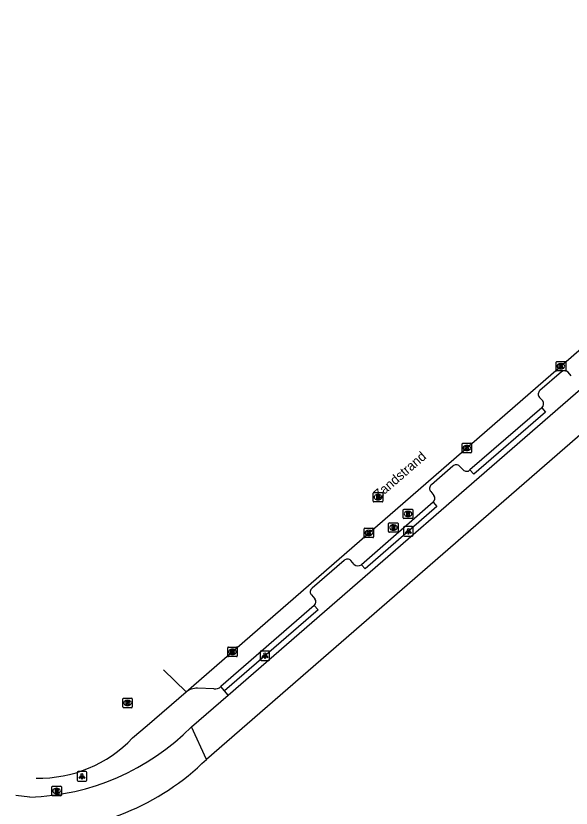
# Model space of a CAD drawing. Extents: x 155640 to 156810, y 382822 to 384046.
# Drawn here: x 156392.5 to 156451, y 383942 to 384025.5 of the extents above; entities that cross this region are included whole.
import ezdxf

# ---------------------------------------------------------------- set-up
doc = ezdxf.new("R2010")
doc.units = 0
for name, color, linetype in [('IMGEO_Berm_groen', 7, 'Continuous'), ('IMGEO_Berm_open', 7, 'Continuous'), ('IMGEO_Fietspad_gesloten', 7, 'Continuous'), ('IMGEO_Kolk', 7, 'Continuous'), ('IMGEO_Lichtpunt', 7, 'Continuous'), ('IMGEO_Openbare_ruimte_label', 7, 'Continuous'), ('IMGEO_Parkeervlak_open', 7, 'Continuous'), ('IMGEO_Rijbaan_lokaal_gesloten', 7, 'Continuous'), ('IMGEO_Rioolput', 7, 'Continuous'), ('IMGEO_Verkeerseiland_open', 7, 'Continuous')]:
    doc.layers.add(name, color=color, linetype=linetype)

msp = doc.modelspace()

# ---------------------------------------------------------------- linework, layer by layer
at = {"layer": 'IMGEO_Berm_groen'}
msp.add_lwpolyline([(156414.861, 383953.961), (156414.47, 383954.414)], dxfattribs=at)
at = {"layer": 'IMGEO_Berm_open'}
for points in [[(156447.898, 383984.213), (156448.29, 383983.759), (156440.715, 383977.209), (156440.323, 383977.663)], [(156423.925, 383963.387), (156424.318, 383962.933), (156414.47, 383954.414)], [(156414.47, 383954.414), (156414.077, 383954.868)]]:
    msp.add_lwpolyline(points, dxfattribs=at)
at = {"layer": 'IMGEO_Fietspad_gesloten'}
for points in [[(156493.456, 384017.313), (156481.006, 384006.405), (156479.158, 384005), (156473.402, 384000), (156464.513, 383992.278), (156412.558, 383947.186)], [(156414.861, 383953.961), (156456.26, 383989.906)], [(156410.985, 383950.596), (156414.861, 383953.961)], [(156412.558, 383947.186), (156410.985, 383950.596)], [(156393.957, 383943.215), (156392.486, 383943.386)]]:
    msp.add_lwpolyline(points, dxfattribs=at)
for centre, radius, start, end in [((156393.202, 383968.289), 25.085, 271.72451, 315.14534), ((156394.176, 383965.799), 26.16, 269.75761, 314.64317)]:
    msp.add_arc(centre, radius, start, end, dxfattribs=at)
at = {"layer": 'IMGEO_Kolk'}
for p, q in [((156449.405, 383988.162), (156449.405, 383989.014)), ((156449.48, 383989.088), (156450.332, 383989.088)), ((156449.893, 383988.868), (156449.918, 383988.868)), ((156450.406, 383989.014), (156450.406, 383988.162)), ((156450.332, 383988.088), (156449.48, 383988.088)), ((156449.916, 383988.308), (156449.891, 383988.308)), ((156439.498, 383979.551), (156439.498, 383980.403)), ((156439.573, 383980.477), (156440.425, 383980.477)), ((156439.986, 383980.257), (156440.011, 383980.257)), ((156440.499, 383980.403), (156440.499, 383979.551)), ((156440.425, 383979.477), (156439.573, 383979.477)), ((156440.009, 383979.697), (156439.984, 383979.697)), ((156429.17, 383970.608), (156429.17, 383971.46)), ((156429.245, 383971.534), (156430.097, 383971.534)), ((156429.658, 383971.314), (156429.683, 383971.314)), ((156430.171, 383971.46), (156430.171, 383970.608)), ((156430.097, 383970.534), (156429.245, 383970.534)), ((156429.681, 383970.754), (156429.656, 383970.754)), ((156414.804, 383958.086), (156414.804, 383958.938)), ((156414.879, 383959.012), (156415.731, 383959.012)), ((156415.292, 383958.792), (156415.317, 383958.792)), ((156415.805, 383958.938), (156415.805, 383958.086)), ((156415.731, 383958.012), (156414.879, 383958.012)), ((156415.315, 383958.232), (156415.29, 383958.232))]:
    msp.add_line(p, q, dxfattribs=at)
for points in [[(156449.405, 383988.162), (156449.405, 383989.014)], [(156449.48, 383989.088), (156450.332, 383989.088)], [(156449.726, 383988.788), (156449.849, 383988.788), (156449.849, 383988.637), (156449.979, 383988.788), (156450.143, 383988.788), (156449.997, 383988.637), (156450.15, 383988.388), (156449.998, 383988.388), (156449.913, 383988.552), (156449.849, 383988.485), (156449.849, 383988.388), (156449.726, 383988.388), (156449.726, 383988.788)], [(156450.406, 383989.014), (156450.406, 383988.162)], [(156450.332, 383988.088), (156449.48, 383988.088)], [(156439.498, 383979.551), (156439.498, 383980.403)], [(156439.573, 383980.477), (156440.425, 383980.477)], [(156439.819, 383980.177), (156439.942, 383980.177), (156439.942, 383980.026), (156440.072, 383980.177), (156440.236, 383980.177), (156440.09, 383980.026), (156440.243, 383979.777), (156440.091, 383979.777), (156440.006, 383979.941), (156439.942, 383979.874), (156439.942, 383979.777), (156439.819, 383979.777), (156439.819, 383980.177)], [(156440.499, 383980.403), (156440.499, 383979.551)], [(156440.425, 383979.477), (156439.573, 383979.477)], [(156429.17, 383970.608), (156429.17, 383971.46)], [(156429.245, 383971.534), (156430.097, 383971.534)], [(156429.491, 383971.234), (156429.614, 383971.234), (156429.614, 383971.083), (156429.744, 383971.234), (156429.908, 383971.234), (156429.762, 383971.083), (156429.915, 383970.834), (156429.763, 383970.834), (156429.678, 383970.998), (156429.614, 383970.931), (156429.614, 383970.834), (156429.491, 383970.834), (156429.491, 383971.234)], [(156430.171, 383971.46), (156430.171, 383970.608)], [(156430.097, 383970.534), (156429.245, 383970.534)], [(156414.804, 383958.086), (156414.804, 383958.938)], [(156414.879, 383959.012), (156415.731, 383959.012)], [(156415.125, 383958.712), (156415.248, 383958.712), (156415.248, 383958.561), (156415.378, 383958.712), (156415.542, 383958.712), (156415.396, 383958.561), (156415.549, 383958.312), (156415.397, 383958.312), (156415.312, 383958.476), (156415.248, 383958.409), (156415.248, 383958.312), (156415.125, 383958.312), (156415.125, 383958.712)], [(156415.805, 383958.938), (156415.805, 383958.086)], [(156415.731, 383958.012), (156414.879, 383958.012)]]:
    msp.add_lwpolyline(points, dxfattribs=at)
for centre, start, end in [((156449.482, 383989.012), 91.55205, 178.44795), ((156449.482, 383989.012), 91.55205, 178.44795), ((156450.33, 383989.012), 1.55205, 88.44795), ((156450.33, 383989.012), 1.55205, 88.44795), ((156449.482, 383988.164), 181.55205, 268.44795), ((156449.482, 383988.164), 181.55205, 268.44795), ((156450.33, 383988.164), 271.55205, 358.44795), ((156450.33, 383988.164), 271.55205, 358.44795), ((156439.575, 383980.401), 91.55205, 178.44795), ((156439.575, 383980.401), 91.55205, 178.44795), ((156440.423, 383980.401), 1.55205, 88.44795), ((156440.423, 383980.401), 1.55205, 88.44795), ((156439.575, 383979.553), 181.55205, 268.44795), ((156439.575, 383979.553), 181.55205, 268.44795), ((156440.423, 383979.553), 271.55205, 358.44795), ((156440.423, 383979.553), 271.55205, 358.44795), ((156429.247, 383971.458), 91.55205, 178.44795), ((156429.247, 383971.458), 91.55205, 178.44795), ((156430.095, 383971.458), 1.55205, 88.44795), ((156430.095, 383971.458), 1.55205, 88.44795), ((156429.247, 383970.61), 181.55205, 268.44795), ((156429.247, 383970.61), 181.55205, 268.44795), ((156430.095, 383970.61), 271.55205, 358.44795), ((156430.095, 383970.61), 271.55205, 358.44795), ((156414.881, 383958.936), 91.55205, 178.44795), ((156414.881, 383958.936), 91.55205, 178.44795), ((156415.729, 383958.936), 1.55205, 88.44795), ((156415.729, 383958.936), 1.55205, 88.44795), ((156414.881, 383958.088), 181.55205, 268.44795), ((156414.881, 383958.088), 181.55205, 268.44795), ((156415.729, 383958.088), 271.55205, 358.44795), ((156415.729, 383958.088), 271.55205, 358.44795)]:
    msp.add_arc(centre, 0.0765, start, end, dxfattribs=at)
for centre, major_axis, ratio, start_param, end_param in [((156449.892, 383988.588), (-0.387, 0.002), 0.722429, 4.712389, 7.853982), ((156449.917, 383988.588), (-0.39, 0.002), 0.717154, 1.570796, 4.712389), ((156439.985, 383979.977), (-0.387, 0.002), 0.722429, 4.712389, 7.853982), ((156440.01, 383979.977), (-0.39, 0.002), 0.717154, 1.570796, 4.712389), ((156429.657, 383971.034), (-0.387, 0.002), 0.722429, 4.712389, 7.853982), ((156429.682, 383971.034), (-0.39, 0.002), 0.717154, 1.570796, 4.712389), ((156415.291, 383958.512), (-0.387, 0.002), 0.722429, 4.712389, 7.853982), ((156415.316, 383958.512), (-0.39, 0.002), 0.717154, 1.570796, 4.712389)]:
    msp.add_ellipse(centre, major_axis=major_axis, ratio=ratio, start_param=start_param, end_param=end_param, dxfattribs=at)
at = {"layer": 'IMGEO_Lichtpunt'}
for p, q in [((156433.331, 383971.601), (156433.331, 383970.794)), ((156433.331, 383971.601), (156433.331, 383970.794)), ((156434.233, 383971.696), (156433.425, 383971.696)), ((156434.233, 383971.696), (156433.425, 383971.696)), ((156434.327, 383970.794), (156434.327, 383971.601)), ((156434.327, 383970.794), (156434.327, 383971.601)), ((156433.425, 383970.7), (156434.233, 383970.7)), ((156433.425, 383970.7), (156434.233, 383970.7)), ((156418.22, 383958.497), (156418.22, 383957.69)), ((156418.22, 383958.497), (156418.22, 383957.69)), ((156419.122, 383958.592), (156418.314, 383958.592)), ((156419.122, 383958.592), (156418.314, 383958.592)), ((156419.216, 383957.69), (156419.216, 383958.497)), ((156419.216, 383957.69), (156419.216, 383958.497)), ((156418.314, 383957.596), (156419.122, 383957.596)), ((156418.314, 383957.596), (156419.122, 383957.596)), ((156398.955, 383945.801), (156398.955, 383944.994)), ((156398.955, 383945.801), (156398.955, 383944.994)), ((156399.857, 383945.896), (156399.049, 383945.896)), ((156399.857, 383945.896), (156399.049, 383945.896)), ((156399.951, 383944.994), (156399.951, 383945.801)), ((156399.951, 383944.994), (156399.951, 383945.801)), ((156399.049, 383944.9), (156399.857, 383944.9)), ((156399.049, 383944.9), (156399.857, 383944.9))]:
    msp.add_line(p, q, dxfattribs=at)
for points in [[(156433.705, 383971.265), (156433.744, 383971.237), (156433.556, 383970.975), (156433.518, 383971.002), (156433.705, 383971.265)], [(156433.807, 383971.217), (156433.854, 383971.217), (156433.854, 383970.895), (156433.807, 383970.895), (156433.807, 383971.217)], [(156433.917, 383971.237), (156433.955, 383971.264), (156434.142, 383971.002), (156434.103, 383970.974), (156433.917, 383971.237)], [(156418.594, 383958.161), (156418.633, 383958.133), (156418.445, 383957.871), (156418.407, 383957.898), (156418.594, 383958.161)], [(156418.696, 383958.113), (156418.743, 383958.113), (156418.743, 383957.791), (156418.696, 383957.791), (156418.696, 383958.113)], [(156418.806, 383958.133), (156418.844, 383958.16), (156419.031, 383957.898), (156418.992, 383957.87), (156418.806, 383958.133)], [(156399.329, 383945.465), (156399.368, 383945.437), (156399.18, 383945.175), (156399.142, 383945.202), (156399.329, 383945.465)], [(156399.431, 383945.417), (156399.478, 383945.417), (156399.478, 383945.095), (156399.431, 383945.095), (156399.431, 383945.417)], [(156399.541, 383945.437), (156399.579, 383945.464), (156399.766, 383945.202), (156399.727, 383945.174), (156399.541, 383945.437)]]:
    msp.add_lwpolyline(points, dxfattribs=at)
for centre in [(156433.83, 383971.399), (156418.719, 383958.295), (156399.454, 383945.599)]:
    msp.add_circle(centre, 0.0994, dxfattribs=at)
for centre, start, end in [((156433.425, 383971.601), 90, 180), ((156433.425, 383971.601), 90, 180), ((156434.233, 383971.601), 0, 90), ((156434.233, 383971.601), 0, 90), ((156433.425, 383970.794), 180, 270), ((156433.425, 383970.794), 180, 270), ((156434.233, 383970.794), 270, 0), ((156434.233, 383970.794), 270, 360), ((156418.314, 383958.497), 90, 180), ((156418.314, 383958.497), 90, 180), ((156419.122, 383958.497), 0, 90), ((156419.122, 383958.497), 0, 90), ((156418.314, 383957.69), 180, 270), ((156418.314, 383957.69), 180, 270), ((156419.122, 383957.69), 270, 0), ((156419.122, 383957.69), 270, 360), ((156399.049, 383945.801), 90, 180), ((156399.049, 383945.801), 90, 180), ((156399.857, 383945.801), 0, 90), ((156399.857, 383945.801), 0, 90), ((156399.049, 383944.994), 180, 270), ((156399.049, 383944.994), 180, 270), ((156399.857, 383944.994), 270, 0), ((156399.857, 383944.994), 270, 360)]:
    msp.add_arc(centre, 0.0946, start, end, dxfattribs=at)
at = {"layer": 'IMGEO_Parkeervlak_open'}
for points in [[(156449.952, 383988.008), (156447.687, 383986.029)], [(156450.979, 383987.562), (156450.66, 383987.952)], [(156447.646, 383985.308), (156447.996, 383984.946)], [(156447.898, 383984.213), (156440.323, 383977.663)], [(156438.527, 383978.052), (156436.252, 383976.1)], [(156439.61, 383977.693), (156439.22, 383978.062)], [(156436.198, 383975.388), (156436.521, 383974.98)], [(156436.433, 383974.258), (156428.88, 383967.689)], [(156427.072, 383968.125), (156423.706, 383965.202)], [(156428.138, 383967.709), (156427.779, 383968.123)], [(156423.635, 383964.5), (156423.967, 383964.105)], [(156423.925, 383963.387), (156414.077, 383954.868)], [(156413.339, 383954.6), (156411.614, 383954.679)]]:
    msp.add_lwpolyline(points, dxfattribs=at)
for centre, radius, start, end in [((156450.278, 383987.62), 0.506, 40.93925, 130.01584), ((156448.013, 383985.649), 0.501, 130.62046, 222.87025), ((156447.513, 383984.638), 0.573, 312.23297, 32.53679), ((156438.878, 383977.747), 0.465, 42.62481, 139.02863), ((156439.98, 383978.004), 0.484, 220.05517, 315.12615), ((156436.553, 383975.719), 0.486, 128.33312, 222.99256), ((156436.078, 383974.668), 0.542, 310.93137, 35.17035), ((156427.425, 383967.805), 0.476, 41.94298, 137.73286), ((156428.521, 383968.141), 0.577, 228.46232, 308.44971), ((156423.949, 383964.823), 0.45, 122.67621, 225.77333), ((156423.585, 383963.767), 0.51, 311.83835, 41.46616), ((156411.595, 383952.794), 1.885, 89.42774, 127.67686), ((156413.462, 383955.412), 0.821, 261.38744, 318.52889)]:
    msp.add_arc(centre, radius, start, end, dxfattribs=at)
at = {"layer": 'IMGEO_Rijbaan_lokaal_gesloten'}
for points in [[(156410.443, 383954.286), (156459.568, 383997.014), (156463.008, 384000), (156492.381, 384025.493)], [(156410.443, 383954.286), (156408.038, 383956.623)], [(156404.786, 383949.438), (156406.325, 383950.745), (156410.443, 383954.286)]]:
    msp.add_lwpolyline(points, dxfattribs=at)
msp.add_arc((156394.915, 383958.833), 13.627, 268.79468, 316.41322, dxfattribs=at)
at = {"layer": 'IMGEO_Rioolput'}
for p, q in [((156430.133, 383974.373), (156430.133, 383975.225)), ((156430.208, 383975.299), (156431.06, 383975.299)), ((156431.134, 383975.225), (156431.134, 383974.373)), ((156431.06, 383974.299), (156430.208, 383974.299)), ((156430.644, 383974.519), (156430.619, 383974.519)), ((156430.621, 383975.079), (156430.646, 383975.079)), ((156433.297, 383972.609), (156433.297, 383973.461)), ((156433.372, 383973.535), (156434.224, 383973.535)), ((156434.298, 383973.461), (156434.298, 383972.609)), ((156433.808, 383972.755), (156433.783, 383972.755)), ((156433.785, 383973.315), (156433.81, 383973.315)), ((156431.754, 383971.172), (156431.754, 383972.024)), ((156431.829, 383972.098), (156432.681, 383972.098)), ((156432.242, 383971.878), (156432.267, 383971.878)), ((156432.755, 383972.024), (156432.755, 383971.172)), ((156434.224, 383972.535), (156433.372, 383972.535)), ((156432.681, 383971.098), (156431.829, 383971.098)), ((156432.265, 383971.318), (156432.24, 383971.318)), ((156403.751, 383952.702), (156403.751, 383953.554)), ((156403.826, 383953.628), (156404.678, 383953.628)), ((156404.752, 383953.554), (156404.752, 383952.702)), ((156404.678, 383952.628), (156403.826, 383952.628)), ((156404.262, 383952.848), (156404.237, 383952.848)), ((156404.239, 383953.408), (156404.264, 383953.408)), ((156396.279, 383943.428), (156396.279, 383944.28)), ((156396.354, 383944.354), (156397.206, 383944.354)), ((156397.28, 383944.28), (156397.28, 383943.428)), ((156396.79, 383943.574), (156396.765, 383943.574)), ((156396.767, 383944.134), (156396.792, 383944.134)), ((156397.206, 383943.354), (156396.354, 383943.354))]:
    msp.add_line(p, q, dxfattribs=at)
for points in [[(156430.133, 383974.373), (156430.133, 383975.225)], [(156430.208, 383975.299), (156431.06, 383975.299)], [(156431.134, 383975.225), (156431.134, 383974.373)], [(156431.06, 383974.299), (156430.208, 383974.299)], [(156430.722, 383974.997), (156430.47, 383974.999), (156430.47, 383974.599)], [(156430.47, 383974.599), (156430.594, 383974.599), (156430.594, 383974.761), (156430.605, 383974.761)], [(156430.648, 383974.918), (156430.594, 383974.918), (156430.594, 383974.837)], [(156430.594, 383974.837), (156430.646, 383974.837)], [(156430.652, 383974.732), (156430.723, 383974.599), (156430.863, 383974.599), (156430.798, 383974.725)], [(156433.297, 383972.609), (156433.297, 383973.461)], [(156433.372, 383973.535), (156434.224, 383973.535)], [(156434.298, 383973.461), (156434.298, 383972.609)], [(156433.886, 383973.233), (156433.634, 383973.235), (156433.634, 383972.835)], [(156433.634, 383972.835), (156433.758, 383972.835), (156433.758, 383972.997), (156433.769, 383972.997)], [(156433.812, 383973.154), (156433.758, 383973.154), (156433.758, 383973.073)], [(156433.758, 383973.073), (156433.81, 383973.073)], [(156433.816, 383972.968), (156433.887, 383972.835), (156434.027, 383972.835), (156433.962, 383972.961)], [(156431.754, 383971.172), (156431.754, 383972.024)], [(156431.829, 383972.098), (156432.681, 383972.098)], [(156432.343, 383971.796), (156432.091, 383971.798), (156432.091, 383971.398)], [(156432.755, 383972.024), (156432.755, 383971.172)], [(156434.224, 383972.535), (156433.372, 383972.535)], [(156432.681, 383971.098), (156431.829, 383971.098)], [(156432.091, 383971.398), (156432.215, 383971.398), (156432.215, 383971.56), (156432.226, 383971.56)], [(156432.269, 383971.717), (156432.215, 383971.717), (156432.215, 383971.636)], [(156432.215, 383971.636), (156432.267, 383971.636)], [(156432.273, 383971.531), (156432.344, 383971.398), (156432.484, 383971.398), (156432.419, 383971.524)], [(156403.751, 383952.702), (156403.751, 383953.554)], [(156403.826, 383953.628), (156404.678, 383953.628)], [(156404.752, 383953.554), (156404.752, 383952.702)], [(156404.678, 383952.628), (156403.826, 383952.628)], [(156404.34, 383953.326), (156404.088, 383953.328), (156404.088, 383952.928)], [(156404.088, 383952.928), (156404.212, 383952.928), (156404.212, 383953.09), (156404.223, 383953.09)], [(156404.266, 383953.247), (156404.212, 383953.247), (156404.212, 383953.166)], [(156404.212, 383953.166), (156404.264, 383953.166)], [(156404.27, 383953.061), (156404.341, 383952.928), (156404.481, 383952.928), (156404.416, 383953.054)], [(156396.279, 383943.428), (156396.279, 383944.28)], [(156396.354, 383944.354), (156397.206, 383944.354)], [(156397.28, 383944.28), (156397.28, 383943.428)], [(156396.868, 383944.052), (156396.616, 383944.054), (156396.616, 383943.654)], [(156396.616, 383943.654), (156396.74, 383943.654), (156396.74, 383943.816), (156396.751, 383943.816)], [(156396.794, 383943.973), (156396.74, 383943.973), (156396.74, 383943.892)], [(156396.74, 383943.892), (156396.792, 383943.892)], [(156396.798, 383943.787), (156396.869, 383943.654), (156397.009, 383943.654), (156396.944, 383943.78)], [(156397.206, 383943.354), (156396.354, 383943.354)]]:
    msp.add_lwpolyline(points, dxfattribs=at)
for centre, radius, start, end in [((156430.21, 383975.223), 0.0765, 91.55205, 178.44795), ((156430.21, 383975.223), 0.0765, 91.55205, 178.44795), ((156431.058, 383975.223), 0.0765, 1.55205, 88.44795), ((156431.058, 383975.223), 0.0765, 1.55205, 88.44795), ((156430.21, 383974.375), 0.0765, 181.55205, 268.44795), ((156430.21, 383974.375), 0.0765, 181.55205, 268.44795), ((156430.604, 383974.708), 0.0533, 26.02933, 88.69889), ((156430.63, 383975.026), 0.19, 274.7715, 282.96867), ((156430.654, 383974.822), 0.0964, 77.00612, 93.18647), ((156430.668, 383974.879), 0.0378, 276.66336, 79.67722), ((156430.721, 383974.887), 0.109, 350.36119, 89.41601), ((156430.719, 383974.887), 0.112, 277.58423, 350.98172), ((156430.703, 383974.672), 0.108, 29.51342, 73.79051), ((156431.058, 383974.375), 0.0765, 271.55205, 358.44795), ((156431.058, 383974.375), 0.0765, 271.55205, 358.44795), ((156433.374, 383973.459), 0.0765, 91.55205, 178.44795), ((156433.374, 383973.459), 0.0765, 91.55205, 178.44795), ((156434.222, 383973.459), 0.0765, 1.55205, 88.44795), ((156434.222, 383973.459), 0.0765, 1.55205, 88.44795), ((156433.768, 383972.944), 0.0533, 26.02933, 88.69889), ((156433.794, 383973.262), 0.19, 274.7715, 282.96867), ((156433.818, 383973.058), 0.0964, 77.00612, 93.18647), ((156433.832, 383973.115), 0.0378, 276.66336, 79.67722), ((156433.885, 383973.123), 0.109, 350.36119, 89.41601), ((156433.883, 383973.123), 0.112, 277.58423, 350.98172), ((156433.867, 383972.908), 0.108, 29.51342, 73.79051), ((156431.831, 383972.022), 0.0765, 91.55205, 178.44795), ((156431.831, 383972.022), 0.0765, 91.55205, 178.44795), ((156432.342, 383971.686), 0.109, 350.36119, 89.41601), ((156432.679, 383972.022), 0.0765, 1.55205, 88.44795), ((156432.679, 383972.022), 0.0765, 1.55205, 88.44795), ((156433.374, 383972.611), 0.0765, 181.55205, 268.44795), ((156433.374, 383972.611), 0.0765, 181.55205, 268.44795), ((156434.222, 383972.611), 0.0765, 271.55205, 358.44795), ((156434.222, 383972.611), 0.0765, 271.55205, 358.44795), ((156431.831, 383971.174), 0.0765, 181.55205, 268.44795), ((156431.831, 383971.174), 0.0765, 181.55205, 268.44795), ((156432.225, 383971.507), 0.0533, 26.02933, 88.69889), ((156432.251, 383971.825), 0.19, 274.7715, 282.96867), ((156432.275, 383971.621), 0.0964, 77.00612, 93.18647), ((156432.289, 383971.678), 0.0378, 276.66336, 79.67722), ((156432.34, 383971.686), 0.112, 277.58423, 350.98172), ((156432.324, 383971.471), 0.108, 29.51342, 73.79051), ((156432.679, 383971.174), 0.0765, 271.55205, 358.44795), ((156432.679, 383971.174), 0.0765, 271.55205, 358.44795), ((156403.828, 383953.552), 0.0765, 91.55205, 178.44795), ((156403.828, 383953.552), 0.0765, 91.55205, 178.44795), ((156404.676, 383953.552), 0.0765, 1.55205, 88.44795), ((156404.676, 383953.552), 0.0765, 1.55205, 88.44795), ((156403.828, 383952.704), 0.0765, 181.55205, 268.44795), ((156403.828, 383952.704), 0.0765, 181.55205, 268.44795), ((156404.222, 383953.037), 0.0533, 26.02933, 88.69889), ((156404.248, 383953.355), 0.19, 274.7715, 282.96867), ((156404.272, 383953.151), 0.0964, 77.00612, 93.18647), ((156404.286, 383953.208), 0.0378, 276.66336, 79.67722), ((156404.339, 383953.216), 0.109, 350.36119, 89.41601), ((156404.337, 383953.216), 0.112, 277.58423, 350.98172), ((156404.321, 383953.001), 0.108, 29.51342, 73.79051), ((156404.676, 383952.704), 0.0765, 271.55205, 358.44795), ((156404.676, 383952.704), 0.0765, 271.55205, 358.44795), ((156396.356, 383944.278), 0.0765, 91.55205, 178.44795), ((156396.356, 383944.278), 0.0765, 91.55205, 178.44795), ((156397.204, 383944.278), 0.0765, 1.55205, 88.44795), ((156397.204, 383944.278), 0.0765, 1.55205, 88.44795), ((156396.356, 383943.43), 0.0765, 181.55205, 268.44795), ((156396.356, 383943.43), 0.0765, 181.55205, 268.44795), ((156396.75, 383943.763), 0.0533, 26.02933, 88.69889), ((156396.776, 383944.081), 0.19, 274.7715, 282.96867), ((156396.8, 383943.877), 0.0964, 77.00612, 93.18647), ((156396.814, 383943.934), 0.0378, 276.66336, 79.67722), ((156396.867, 383943.942), 0.109, 350.36119, 89.41601), ((156396.865, 383943.942), 0.112, 277.58423, 350.98172), ((156396.849, 383943.727), 0.108, 29.51342, 73.79051), ((156397.204, 383943.43), 0.0765, 271.55205, 358.44795), ((156397.204, 383943.43), 0.0765, 271.55205, 358.44795)]:
    msp.add_arc(centre, radius, start, end, dxfattribs=at)
for centre, major_axis, ratio, start_param, end_param in [((156430.62, 383974.799), (-0.387, 0.002), 0.722429, 4.712389, 7.853982), ((156430.645, 383974.799), (-0.39, 0.002), 0.717154, 1.570796, 4.712389), ((156433.784, 383973.035), (-0.387, 0.002), 0.722429, 4.712389, 7.853982), ((156433.809, 383973.035), (-0.39, 0.002), 0.717154, 1.570796, 4.712389), ((156432.241, 383971.598), (-0.387, 0.002), 0.722429, 4.712389, 7.853982), ((156432.266, 383971.598), (-0.39, 0.002), 0.717154, 1.570796, 4.712389), ((156404.238, 383953.128), (-0.387, 0.002), 0.722429, 4.712389, 7.853982), ((156404.263, 383953.128), (-0.39, 0.002), 0.717154, 1.570796, 4.712389), ((156396.766, 383943.854), (-0.387, 0.002), 0.722429, 4.712389, 7.853982), ((156396.791, 383943.854), (-0.39, 0.002), 0.717154, 1.570796, 4.712389)]:
    msp.add_ellipse(centre, major_axis=major_axis, ratio=ratio, start_param=start_param, end_param=end_param, dxfattribs=at)
at = {"layer": 'IMGEO_Verkeerseiland_open'}
msp.add_lwpolyline([(156436.433, 383974.258), (156436.827, 383973.805), (156429.274, 383967.236), (156428.88, 383967.689)], dxfattribs=at)

# ---------------------------------------------------------------- texts
at = {"layer": 'IMGEO_Openbare_ruimte_label'}
msp.add_text('Zandstrand', height=1, rotation=40.90573, dxfattribs=at).set_placement((156430.69, 383974.512))

doc.saveas('drawing.dxf')
